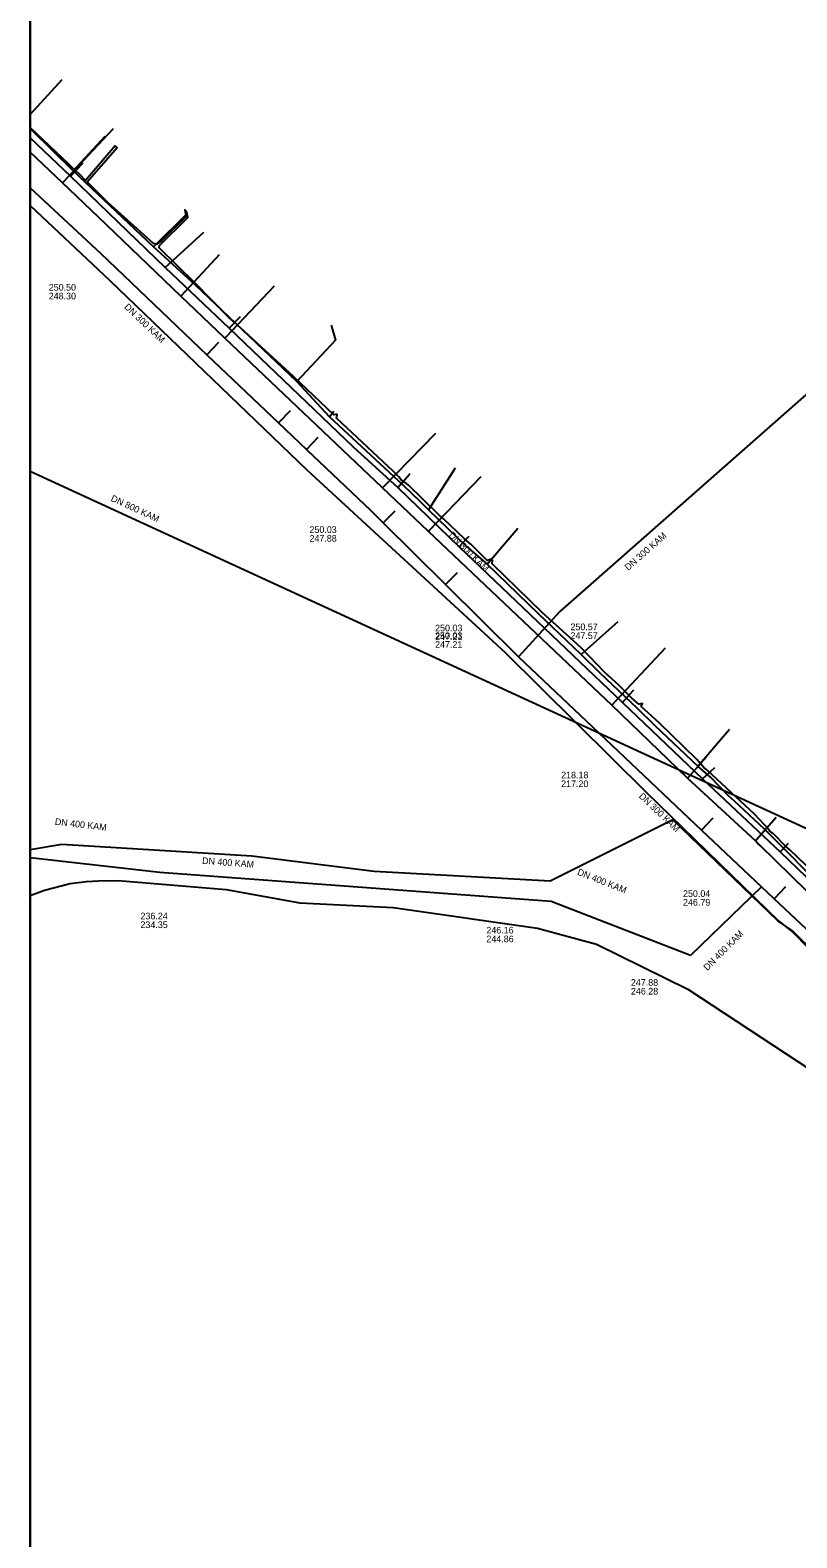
# Model space of a CAD drawing. Extents: x -598233 to -596890, y -1157848 to -1156431.
# Drawn here: x -598232.9 to -598140.8, y -1157178.7 to -1156997.4 of the extents above; entities that cross this region are included whole.
import ezdxf

# ---------------------------------------------------------------- set-up
doc = ezdxf.new("R2010")
doc.units = 0
for name, color, linetype in [('Vrstva 12', 7, 'Continuous'), ('Vrstva 13', 7, 'Continuous'), ('Vrstva 16', 7, 'Continuous'), ('Vrstva 42', 7, 'Continuous'), ('Vrstva 5', 7, 'Continuous'), ('Vrstva 55', 7, 'Continuous'), ('Vrstva 58', 7, 'Continuous'), ('Vrstva 60', 7, 'Continuous'), ('Vrstva 8', 7, 'Continuous'), ('zajmove_uzemi', 7, 'Continuous')]:
    doc.layers.add(name, color=color, linetype=linetype)

msp = doc.modelspace()

# ---------------------------------------------------------------- linework, layer by layer
at = {"layer": 'Vrstva 12'}
for points in [[(-598232.89, -1157009.3), (-598232.73, -1157009.44), (-598227.72, -1157014.36)], [(-598227.72, -1157014.36), (-598223.89, -1157010.21)], [(-598218.06, -1157023.5), (-598227.72, -1157014.36)], [(-598218.06, -1157023.5), (-598213.94, -1157019.43)], [(-598200.84, -1157039.69), (-598213.03, -1157028.12), (-598218.06, -1157023.5)], [(-598196.72, -1157032.9), (-598196.22, -1157034.72), (-598200.84, -1157039.69)], [(-598196.92, -1157043.94), (-598200.84, -1157039.69)], [(-598196.92, -1157043.94), (-598196.4, -1157043.27)], [(-598185.04, -1157055.13), (-598186.01, -1157054.17), (-598188.04, -1157052.21), (-598196.92, -1157043.94)], [(-598181.84, -1157050.1), (-598185.04, -1157055.13)], [(-598185.04, -1157055.13), (-598180.5, -1157059.47), (-598178.01, -1157061.67)], [(-598178.01, -1157061.67), (-598174.33, -1157057.33)], [(-598166.72, -1157072.5), (-598171.81, -1157067.62), (-598178.01, -1157061.67)], [(-598162.31, -1157068.59), (-598166.72, -1157072.5)], [(-598166.72, -1157072.5), (-598164.46, -1157074.71), (-598159.99, -1157078.97), (-598157.84, -1157081.07), (-598152.71, -1157085.93)], [(-598152.71, -1157085.93), (-598148.87, -1157081.49)], [(-598136.92, -1157101.32), (-598144.67, -1157093.5), (-598148.3, -1157090.16), (-598149.02, -1157089.51), (-598151.15, -1157087.27), (-598152.71, -1157085.93)]]:
    msp.add_lwpolyline(points, dxfattribs=at)
at = {"layer": 'Vrstva 13'}
for p, q in [((-598232.89, -1157007.58), (-598229.05, -1157003.36)), ((-598163.02, -1157078.6), (-598156.56, -1157071.73))]:
    msp.add_line(p, q, dxfattribs=at)
for points in [[(-598229, -1157015.82), (-598228.92, -1157015.73), (-598222.88, -1157009.28)], [(-598145.51, -1157095.18), (-598145.77, -1157094.92), (-598153.93, -1157087.37), (-598163.02, -1157078.6), (-598185.04, -1157057.71), (-598190.58, -1157052.47), (-598209.5, -1157034.49), (-598214.78, -1157029.43), (-598224.68, -1157019.94), (-598229, -1157015.82), (-598232.89, -1157012.11)], [(-598214.78, -1157029.43), (-598214.72, -1157029.37), (-598210.13, -1157024.43)], [(-598209.5, -1157034.49), (-598209.35, -1157034.31), (-598203.56, -1157028.18)], [(-598190.58, -1157052.47), (-598190.46, -1157052.35), (-598184.17, -1157045.91)], [(-598185.04, -1157057.71), (-598184.91, -1157057.58), (-598178.7, -1157051.1)], [(-598153.93, -1157087.37), (-598153.83, -1157087.26), (-598151.59, -1157084.79)], [(-598145.77, -1157094.92), (-598145.63, -1157094.77), (-598143.27, -1157092.08)], [(-598117.49, -1157122.5), (-598133.22, -1157107.15), (-598133.96, -1157106.49), (-598145.19, -1157095.49), (-598145.51, -1157095.18)]]:
    msp.add_lwpolyline(points, dxfattribs=at)
at = {"layer": 'Vrstva 16'}
for points in [[(-598232.89, -1157010.41), (-598228.03, -1157015.01), (-598216.67, -1157025.98), (-598209, -1157033.29), (-598194.08, -1157047.55), (-598188.74, -1157052.44), (-598181.34, -1157059.56), (-598161.72, -1157078.28), (-598152.13, -1157087.48), (-598142.82, -1157096.26), (-598129.53, -1157109), (-598117.61, -1157120.7), (-598114.38, -1157121.62), (-598104.58, -1157117.29), (-598096.44, -1157113.56)], [(-598228.03, -1157015.01), (-598226.59, -1157013.47), (-598226.52, -1157013.4)], [(-598216.67, -1157025.98), (-598212.05, -1157021.75)], [(-598209, -1157033.29), (-598207.71, -1157031.94), (-598207.64, -1157031.87)], [(-598188.74, -1157052.44), (-598187.31, -1157050.82), (-598187.24, -1157050.75)], [(-598181.34, -1157059.56), (-598180.43, -1157058.57), (-598180.16, -1157058.28)], [(-598161.72, -1157078.28), (-598160.45, -1157076.84), (-598160.38, -1157076.76)], [(-598152.13, -1157087.48), (-598150.7, -1157086.16), (-598150.63, -1157086.09)], [(-598142.82, -1157096.26), (-598141.79, -1157095.21)]]:
    msp.add_lwpolyline(points, dxfattribs=at)
at = {"layer": 'Vrstva 42'}
for points in [[(-598213.07, -1157027.87), (-598217.39, -1157023.63), (-598217.35, -1157023.33), (-598213.96, -1157019.98), (-598214.11, -1157019.27), (-598214.21, -1157019.16), (-598214.32, -1157019.05), (-598214.15, -1157019.86), (-598217.13, -1157022.79), (-598217.67, -1157023.19), (-598218.06, -1157023.09), (-598223.58, -1157018.18), (-598226.06, -1157015.7), (-598222.46, -1157011.55), (-598222.56, -1157011.46), (-598222.68, -1157011.36), (-598226.23, -1157015.52), (-598226.93, -1157014.81), (-598227.85, -1157013.95), (-598228.22, -1157013.6), (-598232.84, -1157009.2), (-598232.89, -1157009.16)], [(-598138.88, -1157098.66), (-598141.6, -1157096.04), (-598142.21, -1157095.5), (-598143.62, -1157094.06), (-598144.07, -1157093.71), (-598144.29, -1157093.42), (-598144.67, -1157092.98), (-598145.89, -1157091.7), (-598150.98, -1157086.99), (-598151.6, -1157086.37), (-598151.95, -1157086.1), (-598152.86, -1157085.08), (-598157.34, -1157080.75), (-598159.5, -1157078.77), (-598159.33, -1157078.4), (-598159.79, -1157078.49), (-598160.6, -1157077.76), (-598162.2, -1157076.16), (-598163.85, -1157074.67), (-598166.64, -1157071.8), (-598167.62, -1157070.88), (-598171.37, -1157067.45), (-598177.38, -1157061.63), (-598177.35, -1157061.19), (-598177.41, -1157061.12), (-598177.48, -1157061.05), (-598177.99, -1157061.22), (-598179.97, -1157059.26), (-598180.13, -1157059.13), (-598180.76, -1157058.58), (-598183.19, -1157056.25), (-598183.75, -1157055.75), (-598184.61, -1157054.91), (-598185, -1157054.56), (-598185.69, -1157053.86), (-598187.5, -1157052.12), (-598187.67, -1157051.97), (-598188.34, -1157051.51), (-598188.6, -1157051.15), (-598189.23, -1157050.51), (-598196.11, -1157044.08), (-598196.01, -1157043.68), (-598196.07, -1157043.62), (-598196.43, -1157043.68), (-598201.24, -1157039.1), (-598207.12, -1157033.7), (-598208.02, -1157032.87), (-598208.25, -1157032.62), (-598209.08, -1157031.95), (-598213.07, -1157027.87)]]:
    msp.add_lwpolyline(points, dxfattribs=at)
at = {"layer": 'Vrstva 5'}
for p, q in [((-598232.89, -1157016.42), (-598224.41, -1157024.32)), ((-598210.28, -1157035.02), (-598211.66, -1157036.47)), ((-598132.42, -1157034.86), (-598169.28, -1157067.35)), ((-598201.68, -1157043.22), (-598203.06, -1157044.67)), ((-598198.32, -1157046.42), (-598199.7, -1157047.87)), ((-598189.08, -1157055.28), (-598190.49, -1157056.7)), ((-598181.6, -1157062.68), (-598183, -1157064.1)), ((-598169.28, -1157067.35), (-598174.23, -1157072.78)), ((-598150.87, -1157092.18), (-598152.25, -1157093.63)), ((-598217.3, -1157098.71), (-598232.89, -1157096.96)), ((-598170.31, -1157102.21), (-598217.3, -1157098.71)), ((-598145.06, -1157100.44), (-598153.58, -1157108.71)), ((-598142.14, -1157100.44), (-598143.51, -1157101.9)), ((-598153.58, -1157108.71), (-598170.31, -1157102.21))]:
    msp.add_line(p, q, dxfattribs=at)
for points in [[(-598224.41, -1157024.32), (-598211.66, -1157036.47), (-598203.06, -1157044.67), (-598199.7, -1157047.87), (-598191.98, -1157055.22)], [(-598232.89, -1157050.48), (-598206.1, -1157062.82), (-598164.57, -1157081.95), (-598159.45, -1157084.3)], [(-598191.98, -1157055.22), (-598190.49, -1157056.7), (-598183, -1157064.1), (-598174.23, -1157072.78)], [(-598174.23, -1157072.78), (-598164.57, -1157081.95), (-598152.25, -1157093.63), (-598145.06, -1157100.44)], [(-598159.45, -1157084.3), (-598119.93, -1157102.51), (-598090.13, -1157116.24), (-598070.53, -1157125.26)], [(-598118.31, -1157125.61), (-598130.37, -1157114.26), (-598136.4, -1157108.59), (-598143.51, -1157101.9), (-598145.06, -1157100.44)]]:
    msp.add_lwpolyline(points, dxfattribs=at)
at = {"layer": 'Vrstva 55'}
for points in [[(-598232.89, -1157018.54), (-598223.34, -1157027.56), (-598199.64, -1157050.33)], [(-598199.64, -1157050.33), (-598175.83, -1157072.28)], [(-598175.83, -1157072.28), (-598158.85, -1157089.12), (-598142.96, -1157104.58)], [(-598143.08, -1157104.55), (-598155.7, -1157092.39), (-598170.44, -1157099.75), (-598191.55, -1157098.62), (-598206.28, -1157096.78), (-598229.09, -1157095.36), (-598232.89, -1157096)], [(-598088.39, -1157117.57), (-598108.23, -1157126.82), (-598111.78, -1157127.81), (-598115.6, -1157127.95), (-598120.99, -1157125.83), (-598141.33, -1157105.72), (-598143.08, -1157104.55)], [(-598142.96, -1157104.58), (-598141.27, -1157105.89), (-598135.72, -1157111.59), (-598121.84, -1157125.01), (-598122.77, -1157125.89)]]:
    msp.add_lwpolyline(points, dxfattribs=at)
at = {"layer": 'Vrstva 58'}
for points in [[(-598232.89, -1157101.51), (-598231.18, -1157100.86), (-598228.07, -1157100.04), (-598226.11, -1157099.79), (-598224.68, -1157099.72), (-598222.33, -1157099.7), (-598209.35, -1157100.78)], [(-598209.35, -1157100.78), (-598200.5, -1157102.37), (-598189.27, -1157102.94), (-598171.96, -1157105.41), (-598164.88, -1157107.35), (-598153.88, -1157112.74)], [(-598153.88, -1157112.74), (-598139.16, -1157122.46)]]:
    msp.add_lwpolyline(points, dxfattribs=at)
at = {"layer": 'Vrstva 60'}
msp.add_lwpolyline([(-598232.89, -1156430.86), (-598232.89, -1157835.58), (-598232.81, -1157835.6), (-598231.24, -1157835.95), (-598223.73, -1157837.73), (-598218.75, -1157838.85), (-598190.54, -1157845.18), (-598175.89, -1157848.46), (-598170.51, -1157848.46), (-598170.38, -1157848.22), (-598166.89, -1157841.65), (-598165.3, -1157838.66), (-598164.37, -1157836.9), (-598161.86, -1157832.18), (-598161.19, -1157830.95), (-598160.05, -1157828.86), (-598157.63, -1157824.55), (-598144.71, -1157839.14), (-598136.41, -1157848.46), (-597003.66, -1157848.46)], dxfattribs=at)
at = {"layer": 'zajmove_uzemi'}
msp.add_lwpolyline([(-598232.89, -1156430.86), (-596890.46, -1156430.86), (-596890.46, -1157848.46), (-598232.89, -1157848.46)], close=True, dxfattribs=at)

# ---------------------------------------------------------------- texts
at = {"layer": 'Vrstva 8'}
for s, p in [('250.50', (-598230.66, -1157028.77)), ('248.30', (-598230.66, -1157029.82)), ('250.03', (-598199.34, -1157057.9)), ('247.88', (-598199.34, -1157058.95)), ('250.03', (-598184.25, -1157069.73)), ('250.03', (-598184.25, -1157070.66)), ('247.21', (-598184.25, -1157070.78)), ('250.57', (-598167.99, -1157069.59)), ('247.57', (-598167.99, -1157070.65)), ('247.21', (-598184.25, -1157071.71)), ('218.18', (-598169.11, -1157087.41)), ('217.20', (-598169.11, -1157088.46)), ('250.04', (-598154.47, -1157101.66)), ('246.79', (-598154.47, -1157102.71)), ('236.24', (-598219.64, -1157104.36)), ('234.35', (-598219.64, -1157105.41)), ('246.16', (-598178.09, -1157106.06)), ('244.86', (-598178.09, -1157107.11)), ('247.88', (-598160.73, -1157112.35)), ('246.28', (-598160.73, -1157113.4))]:
    msp.add_text(s, height=0.8, dxfattribs=at).set_placement(p)
for s, rotation, p in [('DN 300 KAM', 316.3873, (-598221.66, -1157030.81)), ('DN 800 KAM', 335.2949, (-598223.28, -1157054.02)), ('DN 300 KAM', 315.2987, (-598182.66, -1157058.24)), ('DN 300 KAM', 41.3676, (-598161.05, -1157062.47)), ('DN 300 KAM', 316.5019, (-598159.84, -1157089.64)), ('DN 400 KAM', 353.515, (-598229.96, -1157092.99)), ('DN 400 KAM', 355.6922, (-598212.26, -1157097.69)), ('DN 400 KAM', 338.3316, (-598167.24, -1157098.97)), ('DN 400 KAM', 45.0345, (-598151.55, -1157110.58))]:
    msp.add_text(s, height=0.8, rotation=rotation, dxfattribs=at).set_placement(p)

doc.saveas('drawing.dxf')
